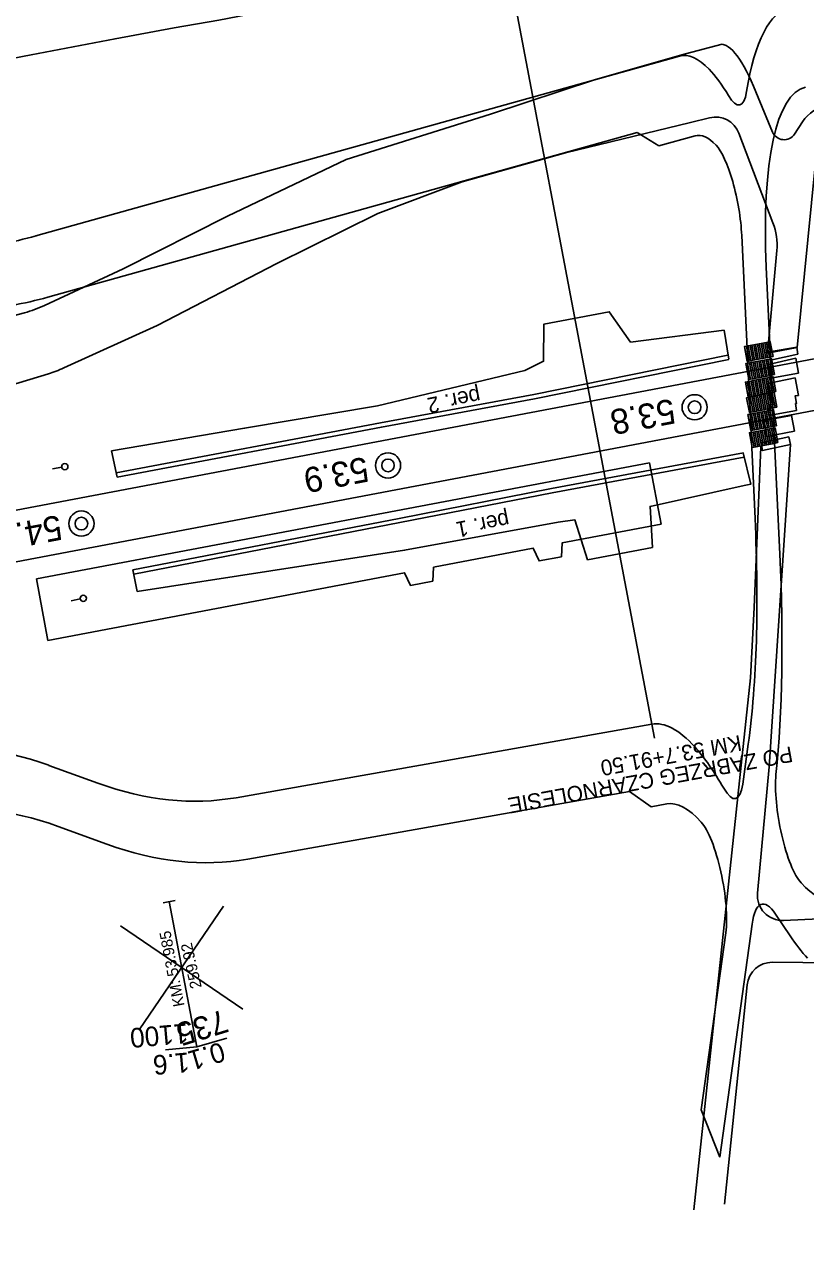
# Model space of a CAD drawing. Extents: x 6541740 to 6566395, y 5525066 to 5530361.
# Drawn here: x 6566013.8 to 6566076.4, y 5528114.5 to 5528212.4 of the extents above; entities that cross this region are included whole.
import ezdxf

# ---------------------------------------------------------------- set-up
doc = ezdxf.new("R2010")
doc.units = 0
for name, color, linetype in [('Domyślna', 7, 'Continuous'), ('ps_wymiarowanie', 7, 'Continuous'), ('TOR_PRZEK_P-pomoc', 7, 'Continuous'), ('TOR_PRZEK_P-uklad odniesienia', 7, 'Continuous'), ('TOR_PS_ODW-osadniki', 7, 'Continuous'), ('TOR_PS_OPIS_T-numeracja torow i rozjazdow', 7, 'Continuous'), ('TOR_PS_OPIS_T-symbole geometrii', 7, 'Continuous'), ('TOR_PS_OPIS_T-ukresy', 7, 'Continuous'), ('TOR_PS_T-rozjazdy projektowane', 7, 'Continuous'), ('TOR_PS_T-umocnienia skarp', 7, 'Continuous'), ('TOR_PS_T-wypelnienia', 7, 'Continuous'), ('TOR_RAMKI-ramka+tabelka 1', 7, 'Continuous')]:
    doc.layers.add(name, color=color, linetype=linetype)

# ---------------------------------------------------------------- blocks, each defined once
blk = doc.blocks.new('POINT_DISPLAY')
at = {"layer": 'Domyślna'}
blk.add_line((0, 0), (0, 0), dxfattribs=at)
blk = doc.blocks.new('4302_59')
at = {"layer": 'Domyślna'}
blk.add_line((0.25, 0), (1, 0), dxfattribs=at)
blk.add_circle((0, 0), 0.25, dxfattribs=at)
blk.add_blockref('POINT_DISPLAY', (0, 0), dxfattribs=at)
blk = doc.blocks.new('4010_1')
at = {"layer": 'Domyślna'}
for radius in [0.75, 0.375]:
    blk.add_circle((0, 0), radius, dxfattribs=at)

msp = doc.modelspace()

# ---------------------------------------------------------------- linework, layer by layer
at = {"layer": 'Domyślna'}
msp.add_line((6566072.832, 5528182.757), (6566072.868, 5528182.713), dxfattribs=at)
for points in [[(6566072.927, 5528185.625), (6566072.703, 5528186.804), (6566072.556, 5528186.776), (6566072.779, 5528185.597)], [(6566073.074, 5528185.653), (6566072.851, 5528186.832), (6566072.703, 5528186.804), (6566072.927, 5528185.625)], [(6566073.222, 5528185.681), (6566072.998, 5528186.86), (6566072.851, 5528186.832), (6566073.074, 5528185.653)], [(6566073.369, 5528185.709), (6566073.145, 5528186.888), (6566072.998, 5528186.86), (6566073.222, 5528185.681)], [(6566073.516, 5528185.737), (6566073.293, 5528186.916), (6566073.145, 5528186.888), (6566073.369, 5528185.709)], [(6566073.664, 5528185.765), (6566073.44, 5528186.944), (6566073.293, 5528186.916), (6566073.516, 5528185.737)], [(6566073.811, 5528185.792), (6566073.588, 5528186.971), (6566073.44, 5528186.944), (6566073.664, 5528185.765)], [(6566071.895, 5528185.429), (6566071.672, 5528186.608), (6566071.524, 5528186.58), (6566071.748, 5528185.401)], [(6566072.043, 5528185.457), (6566071.819, 5528186.636), (6566071.672, 5528186.608), (6566071.895, 5528185.429)], [(6566072.19, 5528185.485), (6566071.966, 5528186.664), (6566071.819, 5528186.636), (6566072.043, 5528185.457)], [(6566072.337, 5528185.513), (6566072.114, 5528186.692), (6566071.966, 5528186.664), (6566072.19, 5528185.485)], [(6566072.485, 5528185.541), (6566072.261, 5528186.72), (6566072.114, 5528186.692), (6566072.337, 5528185.513)], [(6566072.632, 5528185.569), (6566072.409, 5528186.748), (6566072.261, 5528186.72), (6566072.485, 5528185.541)], [(6566072.779, 5528185.597), (6566072.556, 5528186.776), (6566072.409, 5528186.748), (6566072.632, 5528185.569)], [(6566072.018, 5528183.977), (6566071.776, 5528185.254), (6566071.628, 5528185.226), (6566071.87, 5528183.949)], [(6566072.165, 5528184.005), (6566071.923, 5528185.282), (6566071.776, 5528185.254), (6566072.018, 5528183.977)], [(6566072.313, 5528184.033), (6566072.07, 5528185.31), (6566071.923, 5528185.282), (6566072.165, 5528184.005)], [(6566072.46, 5528184.061), (6566072.218, 5528185.338), (6566072.07, 5528185.31), (6566072.313, 5528184.033)], [(6566072.607, 5528184.088), (6566072.365, 5528185.366), (6566072.218, 5528185.338), (6566072.46, 5528184.061)], [(6566072.755, 5528184.116), (6566072.513, 5528185.394), (6566072.365, 5528185.366), (6566072.607, 5528184.088)], [(6566072.902, 5528184.144), (6566072.66, 5528185.422), (6566072.513, 5528185.394), (6566072.755, 5528184.116)], [(6566073.049, 5528184.172), (6566072.807, 5528185.45), (6566072.66, 5528185.422), (6566072.902, 5528184.144)], [(6566073.197, 5528184.2), (6566072.955, 5528185.477), (6566072.807, 5528185.45), (6566073.049, 5528184.172)], [(6566073.344, 5528184.228), (6566073.102, 5528185.505), (6566072.955, 5528185.477), (6566073.197, 5528184.2)], [(6566073.492, 5528184.256), (6566073.249, 5528185.533), (6566073.102, 5528185.505), (6566073.344, 5528184.228)], [(6566073.639, 5528184.284), (6566073.397, 5528185.561), (6566073.249, 5528185.533), (6566073.492, 5528184.256)], [(6566073.786, 5528184.312), (6566073.544, 5528185.589), (6566073.397, 5528185.561), (6566073.639, 5528184.284)], [(6566073.934, 5528184.34), (6566073.692, 5528185.617), (6566073.544, 5528185.589), (6566073.786, 5528184.312)], [(6566072.564, 5528182.706), (6566072.341, 5528183.885), (6566072.193, 5528183.857), (6566072.417, 5528182.678)], [(6566072.711, 5528182.734), (6566072.488, 5528183.913), (6566072.341, 5528183.885), (6566072.564, 5528182.706)], [(6566072.859, 5528182.762), (6566072.635, 5528183.941), (6566072.488, 5528183.913), (6566072.711, 5528182.734)], [(6566073.006, 5528182.79), (6566072.783, 5528183.969), (6566072.635, 5528183.941), (6566072.859, 5528182.762)], [(6566073.154, 5528182.818), (6566072.93, 5528183.997), (6566072.783, 5528183.969), (6566073.006, 5528182.79)], [(6566073.301, 5528182.846), (6566073.077, 5528184.025), (6566072.93, 5528183.997), (6566073.154, 5528182.818)], [(6566073.448, 5528182.874), (6566073.225, 5528184.053), (6566073.077, 5528184.025), (6566073.301, 5528182.846)], [(6566073.596, 5528182.902), (6566073.372, 5528184.081), (6566073.225, 5528184.053), (6566073.448, 5528182.874)], [(6566073.743, 5528182.93), (6566073.52, 5528184.109), (6566073.372, 5528184.081), (6566073.596, 5528182.902)], [(6566073.89, 5528182.958), (6566073.667, 5528184.137), (6566073.52, 5528184.109), (6566073.743, 5528182.93)], [(6566074.038, 5528182.986), (6566073.814, 5528184.165), (6566073.667, 5528184.137), (6566073.89, 5528182.958)], [(6566071.975, 5528182.594), (6566071.751, 5528183.773), (6566071.604, 5528183.746), (6566071.827, 5528182.567)], [(6566072.122, 5528182.622), (6566071.898, 5528183.801), (6566071.751, 5528183.773), (6566071.975, 5528182.594)], [(6566072.269, 5528182.65), (6566072.046, 5528183.829), (6566071.898, 5528183.801), (6566072.122, 5528182.622)], [(6566072.417, 5528182.678), (6566072.193, 5528183.857), (6566072.046, 5528183.829), (6566072.269, 5528182.65)], [(6566074.123, 5528181.73), (6566073.9, 5528182.909), (6566073.752, 5528182.881), (6566073.976, 5528181.702)], [(6566072.06, 5528181.338), (6566071.836, 5528182.517), (6566071.689, 5528182.489), (6566071.913, 5528181.31)], [(6566072.207, 5528181.366), (6566071.984, 5528182.545), (6566071.836, 5528182.517), (6566072.06, 5528181.338)], [(6566072.355, 5528181.394), (6566072.131, 5528182.573), (6566071.984, 5528182.545), (6566072.207, 5528181.366)], [(6566072.502, 5528181.422), (6566072.279, 5528182.601), (6566072.131, 5528182.573), (6566072.355, 5528181.394)], [(6566072.649, 5528181.45), (6566072.426, 5528182.629), (6566072.279, 5528182.601), (6566072.502, 5528181.422)], [(6566072.797, 5528181.478), (6566072.573, 5528182.657), (6566072.426, 5528182.629), (6566072.649, 5528181.45)], [(6566072.944, 5528181.506), (6566072.721, 5528182.685), (6566072.573, 5528182.657), (6566072.797, 5528181.478)], [(6566073.092, 5528181.534), (6566072.868, 5528182.713), (6566072.721, 5528182.685), (6566072.944, 5528181.506)], [(6566073.239, 5528181.562), (6566073.015, 5528182.741), (6566072.868, 5528182.713), (6566073.092, 5528181.534)], [(6566073.386, 5528181.59), (6566073.163, 5528182.769), (6566073.015, 5528182.741), (6566073.239, 5528181.562)], [(6566073.534, 5528181.618), (6566073.31, 5528182.797), (6566073.163, 5528182.769), (6566073.386, 5528181.59)], [(6566073.681, 5528181.646), (6566073.458, 5528182.825), (6566073.31, 5528182.797), (6566073.534, 5528181.618)], [(6566073.828, 5528181.674), (6566073.605, 5528182.853), (6566073.458, 5528182.825), (6566073.681, 5528181.646)], [(6566073.976, 5528181.702), (6566073.752, 5528182.881), (6566073.605, 5528182.853), (6566073.828, 5528181.674)], [(6566072.183, 5528179.886), (6566071.94, 5528181.163), (6566071.793, 5528181.135), (6566072.035, 5528179.858)], [(6566072.33, 5528179.914), (6566072.088, 5528181.191), (6566071.94, 5528181.163), (6566072.183, 5528179.886)], [(6566072.477, 5528179.942), (6566072.235, 5528181.219), (6566072.088, 5528181.191), (6566072.33, 5528179.914)], [(6566072.625, 5528179.97), (6566072.383, 5528181.247), (6566072.235, 5528181.219), (6566072.477, 5528179.942)], [(6566072.772, 5528179.998), (6566072.53, 5528181.275), (6566072.383, 5528181.247), (6566072.625, 5528179.97)], [(6566072.919, 5528180.026), (6566072.677, 5528181.303), (6566072.53, 5528181.275), (6566072.772, 5528179.998)], [(6566073.067, 5528180.053), (6566072.825, 5528181.331), (6566072.677, 5528181.303), (6566072.919, 5528180.026)], [(6566073.214, 5528180.081), (6566072.972, 5528181.359), (6566072.825, 5528181.331), (6566073.067, 5528180.053)], [(6566073.362, 5528180.109), (6566073.12, 5528181.387), (6566072.972, 5528181.359), (6566073.214, 5528180.081)], [(6566073.509, 5528180.137), (6566073.267, 5528181.415), (6566073.12, 5528181.387), (6566073.362, 5528180.109)], [(6566073.656, 5528180.165), (6566073.414, 5528181.442), (6566073.267, 5528181.415), (6566073.509, 5528180.137)], [(6566073.804, 5528180.193), (6566073.562, 5528181.47), (6566073.414, 5528181.442), (6566073.656, 5528180.165)], [(6566073.951, 5528180.221), (6566073.709, 5528181.498), (6566073.562, 5528181.47), (6566073.804, 5528180.193)], [(6566074.098, 5528180.249), (6566073.856, 5528181.526), (6566073.709, 5528181.498), (6566073.951, 5528180.221)], [(6566073.613, 5528178.783), (6566073.39, 5528179.962), (6566073.242, 5528179.934), (6566073.466, 5528178.755)], [(6566073.76, 5528178.811), (6566073.537, 5528179.99), (6566073.39, 5528179.962), (6566073.613, 5528178.783)], [(6566073.908, 5528178.839), (6566073.684, 5528180.018), (6566073.537, 5528179.99), (6566073.76, 5528178.811)], [(6566074.055, 5528178.867), (6566073.832, 5528180.046), (6566073.684, 5528180.018), (6566073.908, 5528178.839)], [(6566074.203, 5528178.895), (6566073.979, 5528180.074), (6566073.832, 5528180.046), (6566074.055, 5528178.867)], [(6566072.287, 5528178.532), (6566072.063, 5528179.711), (6566071.916, 5528179.683), (6566072.139, 5528178.504)], [(6566072.434, 5528178.559), (6566072.211, 5528179.738), (6566072.063, 5528179.711), (6566072.287, 5528178.532)], [(6566072.581, 5528178.587), (6566072.358, 5528179.766), (6566072.211, 5528179.738), (6566072.434, 5528178.559)], [(6566072.729, 5528178.615), (6566072.505, 5528179.794), (6566072.358, 5528179.766), (6566072.581, 5528178.587)], [(6566072.876, 5528178.643), (6566072.653, 5528179.822), (6566072.505, 5528179.794), (6566072.729, 5528178.615)], [(6566073.024, 5528178.671), (6566072.8, 5528179.85), (6566072.653, 5528179.822), (6566072.876, 5528178.643)], [(6566073.171, 5528178.699), (6566072.947, 5528179.878), (6566072.8, 5528179.85), (6566073.024, 5528178.671)], [(6566073.318, 5528178.727), (6566073.095, 5528179.906), (6566072.947, 5528179.878), (6566073.171, 5528178.699)], [(6566073.466, 5528178.755), (6566073.242, 5528179.934), (6566073.095, 5528179.906), (6566073.318, 5528178.727)]]:
    msp.add_lwpolyline(points, close=True, dxfattribs=at)
at = {"layer": 'ps_wymiarowanie'}
for centre, start, end in [((6566011.242, 5528198.947), 285.06172, 294.84499), ((6566012.838, 5528193.972), 286.99513, 294.5218)]:
    msp.add_arc(centre, 10, start, end, dxfattribs=at)
at = {"layer": 'TOR_PRZEK_P-pomoc'}
for p, q in [((6566063.921, 5528177.292), (6566014.796, 5528167.98)), ((6566064.852, 5528172.379), (6566063.921, 5528177.292)), ((6566015.727, 5528163.067), (6566014.796, 5528167.98))]:
    msp.add_line(p, q, dxfattribs=at)
msp.add_lwpolyline([(6566064.852, 5528172.379), (6566056.927, 5528170.877), (6566056.863, 5528169.766), (6566055.07, 5528169.426), (6566054.604, 5528170.436), (6566046.611, 5528168.921), (6566046.547, 5528167.81), (6566044.754, 5528167.47), (6566044.287, 5528168.481), (6566015.727, 5528163.067)], dxfattribs=at)
at = {"layer": 'TOR_PRZEK_P-uklad odniesienia'}
for p, q in [((6566023.091, 5528131.965), (6566029.781, 5528141.784)), ((6566031.346, 5528133.53), (6566021.527, 5528140.219))]:
    msp.add_line(p, q, dxfattribs=at)
at = {"layer": 'TOR_PS_ODW-osadniki'}
for p, q in [((6566025.927, 5528142.246), (6566024.945, 5528142.059)), ((6566025.436, 5528142.153), (6566027.641, 5528130.518)), ((6566027.641, 5528130.518), (6566030.051, 5528131.23)), ((6566027.641, 5528130.518), (6566025.138, 5528130.299))]:
    msp.add_line(p, q, dxfattribs=at)
at = {"layer": 'TOR_PS_OPIS_T-numeracja torow i rozjazdow'}
msp.add_line((6566064.307, 5528155.243), (6566044.931, 5528257.403), dxfattribs=at)
at = {"layer": 'TOR_PS_OPIS_T-symbole geometrii'}
for p, q in [((6566066.323, 5528209.838), (6566014.766, 5528195.448)), ((6566062.915, 5528203.713), (6566015.723, 5528190.542)), ((6566062.915, 5528203.713), (6566064.652, 5528202.646)), ((6566064.652, 5528202.646), (6566067.567, 5528203.46)), ((6566071.303, 5528195.482), (6566072.366, 5528172.835)), ((6566073.273, 5528192.933), (6566074.352, 5528169.955)), ((6566064.09, 5528156.356), (6566030.796, 5528150.473)), ((6566071.378, 5528151.558), (6566071.822, 5528154.758)), ((6566019.709, 5528151.644), (6566015.797, 5528153.062)), ((6566062.301, 5528150.963), (6566031.724, 5528145.56)), ((6566062.301, 5528150.963), (6566064.056, 5528149.75)), ((6566065.295, 5528149.969), (6566064.056, 5528149.75)), ((6566020.45, 5528146.75), (6566016.538, 5528148.169)), ((6566074, 5528141.157), (6566075.177, 5528139.418)), ((6566069.541, 5528121.681), (6566072.131, 5528140.344)), ((6566068.062, 5528125.488), (6566070.027, 5528139.654)), ((6566068.062, 5528125.488), (6566069.541, 5528121.681))]:
    msp.add_line(p, q, dxfattribs=at)
for centre, major_axis, start_param, end_param in [((6566081.444, 5528181.083), (6.192, -32.668), 3.14947, 3.750336), ((6566070.63, 5528187.759), (-4.19, 22.106), 5.91928, 6.304446), ((6566070.63, 5528187.759), (-4.19, 22.106), 5.690078, 5.91928), ((6566070.154, 5528211.089), (-0.978, 5.158), 2.548485, 3.750336), ((6566081.444, 5528181.083), (4.982, -26.282), 3.14947, 4.197854), ((6566070.63, 5528187.759), (-2.98, 15.72), 5.919283, 6.304446), ((6566069.699, 5528197.808), (-0.978, 5.158), 4.197854, 5.919283), ((6565919.537, 5528683.642), (92.653, -488.796), 6.281006, 6.304446), ((6565919.537, 5528683.642), (93.584, -493.709), 6.281006, 6.304446), ((6566055.03, 5528197.974), (-10.569, 55.757), 3.779565, 4.197854), ((6566055.03, 5528197.974), (-11.779, 62.143), 3.841102, 4.197854), ((6566070.118, 5528124.42), (-6.053, 31.931), 5.894354, 6.280077), ((6566060.628, 5527857.002), (-56.337, 297.208), 6.136011, 6.280144), ((6566070.118, 5528124.42), (-6.053, 31.931), 5.65962, 5.894354), ((6565975.618, 5528442.81), (-55.405, 292.295), 2.994419, 3.138484), ((6566069.825, 5528155.556), (-0.978, 5.158), 2.518027, 3.779565), ((6566075.625, 5528148.531), (-0.978, 5.158), 0.699509, 2.759346), ((6566060.628, 5527857.002), (-55.405, 292.295), 6.136011, 6.280144), ((6566070.118, 5528124.42), (-4.842, 25.545), 5.894354, 6.280077), ((6566068.474, 5528143.652), (-0.978, 5.158), 3.779565, 5.894354), ((6565975.618, 5528442.81), (-56.337, 297.208), 2.994419, 3.138484), ((6566073.94, 5528167.807), (4.842, -25.545), 5.900938, 6.272186), ((6566074.276, 5528134.823), (-1.35, 7.123), 5.758206, 6.921158), ((6566073.94, 5528167.807), (6.053, -31.931), 5.758206, 5.900938)]:
    msp.add_ellipse(centre, major_axis=major_axis, ratio=0.25, start_param=start_param, end_param=end_param, dxfattribs=at)
at = {"layer": 'TOR_PS_OPIS_T-ukresy'}
for points in [[(6566025.842, 5528212.104), (6566029.407, 5528212.726), (6566034.103, 5528213.622), (6566039.42, 5528214.668), (6566044.615, 5528215.713), (6566050.162, 5528216.8), (6566054.962, 5528217.714), (6566058.783, 5528218.414), (6566063.776, 5528219.312), (6566069.24, 5528220.364), (6566074.949, 5528221.471), (6566077.406, 5528221.938)], [(6565959.69, 5528199.413), (6565965.258, 5528200.484), (6565968.971, 5528201.2), (6565973.259, 5528202.05), (6565978.894, 5528203.143), (6565984.056, 5528204.128), (6565989.117, 5528205.096), (6565997.957, 5528206.786), (6566002.465, 5528207.655), (6566007.856, 5528208.69), (6566014.367, 5528209.938), (6566021.103, 5528211.229), (6566025.84, 5528212.114)]]:
    msp.add_lwpolyline(points, dxfattribs=at)
at = {"layer": 'TOR_PS_T-rozjazdy projektowane'}
for p, q in [((6566239.09, 5528216.307), (6564914.519, 5527965.231)), ((6566239.844, 5528212.328), (6565011.713, 5527979.532))]:
    msp.add_line(p, q, dxfattribs=at)
at = {"layer": 'TOR_PS_T-umocnienia skarp'}
msp.add_line((6566055.455, 5528188.382), (6566060.691, 5528189.374), dxfattribs=at)
for points in [[(6566069.889, 5528187.891), (6566062.396, 5528186.935), (6566060.691, 5528189.374), (6566055.455, 5528188.382), (6566055.435, 5528185.415), (6566053.917, 5528184.665), (6566042.126, 5528181.85), (6566031.472, 5528180.041), (6566020.818, 5528178.233)], [(6566070.261, 5528185.565), (6566069.889, 5528187.891)], [(6566021.191, 5528176.473), (6566042.369, 5528180.49), (6566054.644, 5528182.756), (6566070.201, 5528185.908)], [(6566021.257, 5528176.129), (6566042.434, 5528180.146), (6566054.71, 5528182.412), (6566070.267, 5528185.564)], [(6566020.818, 5528178.233), (6566021.26, 5528176.131)], [(6566022.53, 5528168.722), (6566022.883, 5528166.99), (6566033.587, 5528168.633), (6566044.291, 5528170.276), (6566056.603, 5528172.542), (6566057.932, 5528172.728), (6566058.958, 5528169.521), (6566064.149, 5528170.505), (6566063.954, 5528173.787), (6566071.508, 5528175.456), (6566072.024, 5528175.562), (6566071.424, 5528178.07)], [(6566071.431, 5528178.075), (6566056.054, 5528175.214), (6566043.847, 5528172.834), (6566022.533, 5528168.72)], [(6566071.496, 5528177.731), (6566056.119, 5528174.87), (6566043.912, 5528172.491), (6566022.598, 5528168.376)]]:
    msp.add_lwpolyline(points, dxfattribs=at)
at = {"layer": 'TOR_PS_T-wypelnienia'}
for p, q in [((6566066.785, 5528210.021), (6566069.722, 5528210.784)), ((6566059.596, 5528207.977), (6566066.785, 5528210.021)), ((6566051.169, 5528205.193), (6566059.596, 5528207.977)), ((6566072.623, 5528206.514), (6566073.772, 5528203.761)), ((6566039.602, 5528201.554), (6566051.169, 5528205.193)), ((6566057.174, 5528202.101), (6566067.199, 5528204.513)), ((6566067.199, 5528204.513), (6566068.726, 5528204.897)), ((6566075.528, 5528203.593), (6566076.183, 5528204.58)), ((6566073.807, 5528196.499), (6566071.082, 5528203.668)), ((6566030.096, 5528197.029), (6566039.602, 5528201.554)), ((6566048.904, 5528199.784), (6566057.174, 5528202.101)), ((6566077.178, 5528201.044), (6566075.742, 5528186.5)), ((6566042.16, 5528197.239), (6566048.904, 5528199.784)), ((6566021.759, 5528192.797), (6566030.096, 5528197.029)), ((6566034.05, 5528193.233), (6566042.16, 5528197.239)), ((6566074.113, 5528194.272), (6566073.369, 5528186.049)), ((6566015.443, 5528189.873), (6566021.759, 5528192.797)), ((6566024.463, 5528188.283), (6566034.05, 5528193.233)), ((6566005.895, 5528187.153), (6566013.84, 5528189.291)), ((6566016.988, 5528184.874), (6566024.463, 5528188.283)), ((6566075.742, 5528186.5), (6566073.369, 5528186.049)), ((6566008.676, 5528182.243), (6566015.761, 5528184.408)), ((6566072.297, 5528165.692), (6566072.82, 5528178.55)), ((6566075.202, 5528178.739), (6566073.496, 5528152.941)), ((6566072.297, 5528165.692), (6566072, 5528160.067)), ((6566072, 5528160.067), (6566071.249, 5528153.066)), ((6566071.249, 5528153.066), (6566067.472, 5528117.474)), ((6566072.568, 5528142.825), (6566073.496, 5528152.941)), ((6566099.541, 5528141.761), (6566074.65, 5528140.645)), ((6566073.753, 5528137.295), (6566098.277, 5528137.028)), ((6566069.935, 5528117.941), (6566071.742, 5528135.499))]:
    msp.add_line(p, q, dxfattribs=at)
for points in [[(6566075.809, 5528185.986), (6566075.709, 5528186.545), (6566073.492, 5528186.171)], [(6566073.492, 5528186.171), (6566073.612, 5528185.498), (6566075.809, 5528185.986)], [(6566075.633, 5528185.645), (6566073.437, 5528185.158), (6566073.639, 5528184.059), (6566075.85, 5528184.457)], [(6566075.85, 5528184.457), (6566075.633, 5528185.645)], [(6566075.577, 5528184.081), (6566073.393, 5528183.635), (6566073.619, 5528182.313), (6566073.603, 5528181.571), (6566073.391, 5528181.534), (6566073.475, 5528181.064), (6566075.697, 5528181.466)], [(6566075.697, 5528181.466), (6566075.619, 5528182.026), (6566075.698, 5528182.04), (6566075.587, 5528182.653), (6566075.849, 5528182.681), (6566075.577, 5528184.081)], [(6566075.299, 5528181.063), (6566073.535, 5528180.735), (6566073.091, 5528180.59), (6566073.311, 5528179.386)], [(6566073.311, 5528179.386), (6566075.528, 5528179.819), (6566075.299, 5528181.063)], [(6566075.083, 5528179.371), (6566072.86, 5528178.871), (6566072.959, 5528178.263), (6566075.202, 5528178.739)], [(6566075.202, 5528178.739), (6566075.083, 5528179.371)]]:
    msp.add_lwpolyline(points, dxfattribs=at)
for centre, radius, start, end in [((6566078.683, 5528202.922), 3, 98.9824, 146.44427), ((6566069.213, 5528202.957), 2, 20.80996, 104.09122), ((6566074.695, 5528204.146), 1, 202.64208, 326.44427), ((6566069.133, 5528194.722), 5, 354.82941, 20.80996), ((6566074.56, 5528142.643), 2, 174.76105, 272.56855), ((6566073.731, 5528135.295), 2, 89.37663, 174.12537)]:
    msp.add_arc(centre, radius, start, end, dxfattribs=at)
msp.add_ellipse((6566071.556, 5528200.018), major_axis=(-2.039, 10.758), ratio=0.25, start_param=5.312543, end_param=6.208798, dxfattribs=at)

# ---------------------------------------------------------------- block references
at = {"layer": 'Domyślna'}
for p, rotation in [((6566017.078, 5528176.974), -169.22680053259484), ((6566018.553, 5528166.432), -168.46559851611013)]:
    msp.add_blockref('4302_59', p, dxfattribs=dict(at, rotation=rotation))
at = {"layer": 'TOR_RAMKI-ramka+tabelka 1', "xscale": 1.345963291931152, "yscale": 1.345963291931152}
for p in [(6566067.529, 5528181.726), (6566042.966, 5528177.07), (6566018.404, 5528172.415)]:
    msp.add_blockref('4010_1', p, dxfattribs=at)

# ---------------------------------------------------------------- texts
at = {"layer": 'TOR_PS_ODW-osadniki'}
for s, height, rotation, p in [('KM: 53.985', 0.9, 100.7323, (6566026.669, 5528133.828)), ('259.92', 0.9082, 102.73942, (6566028.051, 5528135.3)), ('735', 1.8494, 197.22579, (6566029.783, 5528133.542)), ('1100', 1.5695, 185.02171, (6566026.889, 5528132.404)), ('1.6', 1.5695, 185.02171, (6566026.989, 5528130.085)), ('0.1', 1.5692, 196.44289, (6566029.62, 5528130.94))]:
    msp.add_text(s, height=height, rotation=rotation, dxfattribs=at).set_placement(p)
at = {"layer": 'TOR_PS_OPIS_T-numeracja torow i rozjazdow'}
for s, p in [('PO ZABRZEG CZARNOLESIE', (6566075.258, 5528154.594)), ('KM 53.7+91.50', (6566071.16, 5528155.493))]:
    msp.add_text(s, height=1.25603, rotation=190.36859, dxfattribs=at).set_placement(p)
at = {"layer": 'TOR_PS_T-umocnienia skarp'}
for s, p in [('per. 2', (6566050.242, 5528183.278)), ('per. 1', (6566052.552, 5528173.345))]:
    msp.add_text(s, height=1.2566, rotation=191.11515, dxfattribs=at).set_placement(p)
at = {"layer": 'TOR_RAMKI-ramka+tabelka 1'}
for s, p in [('53.8', (6566065.756, 5528182.434)), ('53.9', (6566041.19, 5528177.777)), ('54.0', (6566016.627, 5528173.122))]:
    msp.add_text(s, height=2, rotation=190.76907, dxfattribs=at).set_placement(p)

doc.saveas('drawing.dxf')
